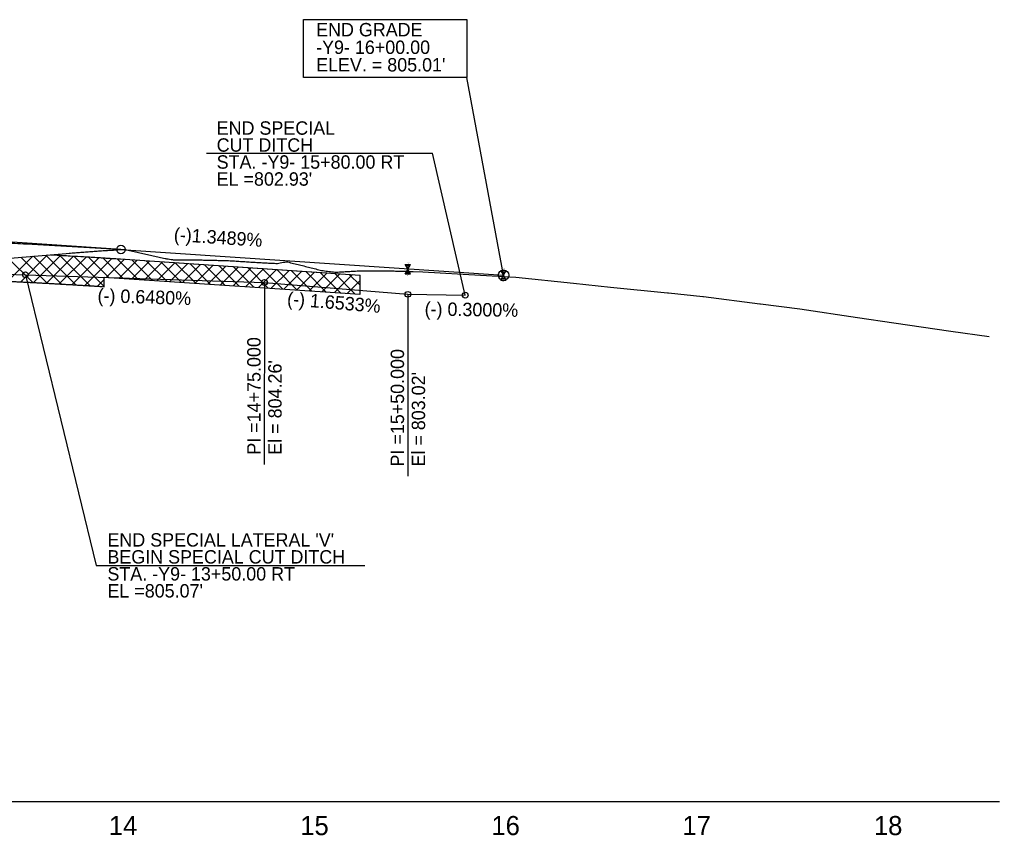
# Model space of a CAD drawing. Extents: x 579185 to 595036, y -53221 to -44640.
# Drawn here: x 591536 to 592048, y -49553 to -49126 of the extents above; entities that cross this region are included whole.
import ezdxf

# ---------------------------------------------------------------- set-up
doc = ezdxf.new("R2010")
doc.units = 0
for name, color, linetype in [('Exist Profile Cell', 7, 'Continuous'), ('Exist Vertical Profile Ground Line', 7, 'Continuous'), ('Exist Vertical Profile Horizontal Axis Label Major', 7, 'Continuous'), ('Old_Level_2', 7, 'Continuous'), ('Prop Grid Mask', 7, 'Continuous'), ('Prop Hatching', 7, 'Continuous'), ('Prop Vertical Profile Curve Label', 7, 'Continuous'), ('Prop Vertical Profile Ditch Grade Right', 7, 'Continuous'), ('Prop Vertical Profile Ditch Grade Right Label', 7, 'Continuous'), ('Prop Vertical Profile Grade', 7, 'Continuous'), ('Prop Vertical Profile Grade Label', 7, 'Continuous'), ('Prop VPI Ditch Grade Right Label', 7, 'Continuous'), ('Prop VPI Label', 7, 'Continuous')]:
    doc.layers.add(name, color=color, linetype=linetype)

msp = doc.modelspace()

# ---------------------------------------------------------------- linework, layer by layer
at = {"layer": 'Exist Profile Cell'}
msp.add_line((591188.99, -49535.12), (592048.25, -49535.12), dxfattribs=at)
at = {"layer": 'Exist Vertical Profile Ground Line'}
for points in [[(591531.14, -49251.08), (591560.27, -49248.66), (591561.87, -49248.52), (591562.64, -49248.46), (591563.41, -49248.4), (591564.18, -49248.34), (591564.96, -49248.27), (591565.73, -49248.21), (591566.5, -49248.15), (591567.27, -49248.09), (591568.05, -49248.03), (591568.82, -49247.97), (591569.59, -49247.91), (591570.36, -49247.85), (591571.13, -49247.79), (591571.91, -49247.73), (591572.78, -49247.66), (591573.45, -49247.61), (591574.22, -49247.56), (591575, -49247.51), (591575.77, -49247.46), (591576.54, -49247.41), (591577.31, -49247.35), (591578.08, -49247.3), (591578.86, -49247.25), (591579.63, -49247.2), (591580.4, -49247.15), (591581.17, -49247.1), (591581.95, -49247.05), (591582.72, -49247.01), (591583.49, -49246.96), (591584.26, -49246.91), (591585.03, -49246.86), (591585.81, -49246.82), (591586.58, -49246.77), (591587.35, -49246.72), (591588.12, -49246.68), (591588.9, -49246.63), (591589.67, -49246.59), (591590.66, -49246.53), (591591.21, -49246.65), (591591.98, -49246.83), (591592.76, -49247)], [(591592.76, -49247), (591593.53, -49247.17), (591594.3, -49247.35), (591595.07, -49247.52), (591595.84, -49247.69), (591596.62, -49247.87), (591597.39, -49248.04), (591598.16, -49248.21), (591598.93, -49248.38), (591599.71, -49248.56), (591600.48, -49248.73), (591601.25, -49248.9), (591602.02, -49249.07), (591602.79, -49249.24), (591603.57, -49249.42), (591604.34, -49249.59), (591605.11, -49249.76), (591605.88, -49249.93), (591606.66, -49250.1), (591607.43, -49250.27), (591608.2, -49250.44), (591608.97, -49250.6), (591609.74, -49250.77), (591610.52, -49250.94), (591611.29, -49251.11), (591612.06, -49251.27), (591612.46, -49251.36), (591612.83, -49251.42), (591613.61, -49251.54), (591614.38, -49251.66), (591615.15, -49251.78), (591615.92, -49251.9), (591616.3, -49251.96), (591616.69, -49251.96), (591617.47, -49251.97), (591618.24, -49251.98), (591619.01, -49251.99), (591619.78, -49252), (591620.72, -49252.01), (591621.33, -49252.01), (591622.1, -49252.02), (591622.87, -49252.02), (591623.64, -49252.02), (591624.42, -49252.03), (591625.19, -49252.03), (591625.96, -49252.04), (591626.73, -49252.04), (591627.51, -49252.05), (591628.28, -49252.05), (591629.05, -49252.06), (591629.82, -49252.07), (591630.59, -49252.07), (591631.37, -49252.08), (591632.14, -49252.09), (591632.91, -49252.1), (591633.68, -49252.11), (591634.46, -49252.13), (591635.23, -49252.15), (591636, -49252.17), (591636.77, -49252.19), (591637.54, -49252.21), (591638.32, -49252.23), (591639.09, -49252.24), (591639.86, -49252.26), (591640.63, -49252.28), (591641.41, -49252.3), (591642.18, -49252.33), (591642.95, -49252.35), (591643.72, -49252.37), (591644.49, -49252.39), (591645.27, -49252.41), (591646.04, -49252.43), (591646.81, -49252.48), (591647.58, -49252.54), (591648.35, -49252.59), (591649.13, -49252.64), (591649.9, -49252.69), (591650.67, -49252.74), (591651.44, -49252.79), (591652.22, -49252.84), (591652.99, -49252.89), (591653.76, -49252.94), (591654.53, -49252.98), (591655.3, -49253.03), (591656.08, -49253.08), (591656.85, -49253.13), (591657.62, -49253.17), (591658.39, -49253.22), (591659.17, -49253.26), (591659.94, -49253.31), (591660.71, -49253.35), (591661.48, -49253.4), (591662.25, -49253.44), (591663.03, -49253.48), (591663.8, -49253.53), (591664.57, -49253.57), (591665.34, -49253.61), (591666.12, -49253.65), (591666.89, -49253.69), (591667.66, -49253.73), (591668.43, -49253.77)], [(591668.43, -49253.77), (591669.2, -49253.81), (591669.98, -49253.85), (591670.75, -49253.88), (591671.52, -49253.73), (591672.29, -49253.58), (591673.07, -49253.44), (591673.84, -49253.29), (591674.61, -49253.14), (591675.52, -49252.96), (591676.15, -49253.12), (591676.93, -49253.3), (591677.7, -49253.49), (591678.47, -49253.68), (591679.24, -49253.87), (591680.02, -49254.06), (591680.79, -49254.25), (591681.56, -49254.44), (591682.33, -49254.63), (591683.1, -49254.83), (591683.88, -49255.02), (591684.65, -49255.21), (591685.42, -49255.41), (591686.19, -49255.6), (591686.97, -49255.8), (591687.74, -49255.99), (591688.51, -49256.19), (591689.28, -49256.38), (591690.05, -49256.58), (591690.83, -49256.78), (591691.6, -49256.98), (591692.37, -49257.17), (591693.14, -49257.37), (591693.91, -49257.49), (591694.69, -49257.61), (591695.46, -49257.73), (591696.23, -49257.84), (591697, -49257.96), (591697.78, -49258.07), (591698.16, -49258.13), (591698.55, -49258.16), (591699.32, -49258.23), (591700.09, -49258.29), (591700.86, -49258.36), (591701.71, -49258.42), (591702.41, -49258.38), (591703.18, -49258.33), (591703.95, -49258.28), (591704.73, -49258.23), (591705.5, -49258.18), (591706.27, -49258.14), (591707.04, -49258.09), (591707.81, -49258.05), (591708.59, -49258.01), (591709.36, -49257.96), (591710.13, -49257.92), (591710.9, -49257.88), (591711.68, -49257.84), (591712.45, -49257.81), (591713.22, -49257.77), (591713.63, -49257.75), (591713.99, -49257.75), (591714.76, -49257.75), (591715.54, -49257.74), (591716.31, -49257.74), (591717.08, -49257.74), (591717.85, -49257.74), (591718.63, -49257.74), (591719.4, -49257.74), (591720.17, -49257.74), (591720.94, -49257.75), (591721.71, -49257.75), (591722.49, -49257.75), (591723.26, -49257.76), (591724.03, -49257.76), (591724.8, -49257.77), (591725.58, -49257.77), (591726.35, -49257.78), (591727.12, -49257.79), (591727.89, -49257.8), (591728.66, -49257.8), (591729.1, -49257.81), (591729.44, -49257.81), (591730.21, -49257.8), (591730.98, -49257.8), (591731.75, -49257.82), (591732.53, -49257.83), (591733.3, -49257.85), (591734.07, -49257.86), (591734.84, -49257.88), (591735.61, -49257.9), (591736.39, -49257.92), (591737.16, -49257.93), (591737.93, -49257.95), (591738.7, -49257.97), (591739.48, -49257.99), (591740.25, -49258.01), (591741.02, -49258.03), (591741.79, -49258.05), (591746.89, -49258.18), (591776.93, -49259.96)], [(591776.93, -49259.96), (591795.5, -49261.06), (591825.5, -49264.18), (591844.97, -49266.21), (591874.77, -49269.23), (591875.18, -49269.27), (591893.16, -49271.1), (591893.57, -49271.15), (591923.05, -49274.95), (591923.36, -49274.99), (591943.99, -49277.65), (591974, -49282.1), (591992.99, -49284.92), (592022.91, -49289.2), (592042.92, -49292.06)]]:
    msp.add_lwpolyline(points, dxfattribs=at)
at = {"layer": 'Old_Level_2'}
for p, q in [((591738.99, -49256.88), (591737.55, -49254.38)), ((591737.55, -49254.38), (591740.43, -49254.38)), ((591738.99, -49256.88), (591740.43, -49254.38)), ((591737.55, -49259.38), (591738.99, -49256.88)), ((591737.55, -49259.38), (591740.43, -49259.38)), ((591738.03, -49255.21), (591739.95, -49255.21)), ((591738.03, -49258.55), (591739.95, -49258.55)), ((591738.51, -49256.05), (591739.47, -49256.05)), ((591738.51, -49257.72), (591739.47, -49257.72)), ((591740.43, -49259.38), (591738.99, -49256.88)), ((591788.99, -49260.04), (591787.55, -49257.54)), ((591787.55, -49257.54), (591790.43, -49257.54)), ((591788.03, -49258.37), (591789.95, -49258.37)), ((591788.51, -49259.21), (591789.47, -49259.21)), ((591788.99, -49260.04), (591790.43, -49257.54)), ((591787.55, -49262.54), (591788.99, -49260.04)), ((591787.55, -49262.54), (591790.43, -49262.54)), ((591788.03, -49261.71), (591789.95, -49261.71)), ((591788.51, -49260.88), (591789.47, -49260.88)), ((591790.43, -49262.54), (591788.99, -49260.04))]:
    msp.add_line(p, q, dxfattribs=at)
at = {"layer": 'Prop Grid Mask'}
msp.add_lwpolyline([(591684.45, -49126.46), (591769.85, -49126.46), (591769.85, -49156.65), (591684.45, -49156.65)], close=True, dxfattribs=at)
at = {"layer": 'Prop Hatching'}
for p, q in [((591529.81, -49263.19), (591542.9, -49250.1)), ((591530.07, -49251.05), (591542.86, -49263.84)), ((591536.55, -49263.52), (591550.62, -49249.46)), ((591536.71, -49250.62), (591550.33, -49264.23)), ((591543.24, -49250.07), (591557.82, -49264.65)), ((591543.29, -49263.86), (591557.53, -49249.61)), ((591549.77, -49249.53), (591565.32, -49265.09)), ((591550, -49264.22), (591564.22, -49250)), ((591556.7, -49264.59), (591570.89, -49250.4)), ((591556.88, -49249.58), (591572.85, -49265.55)), ((591563.39, -49264.97), (591577.55, -49250.81)), ((591564.39, -49250.01), (591580.24, -49265.86)), ((591570.06, -49265.37), (591584.19, -49251.24)), ((591571.91, -49250.46), (591582.61, -49261.16)), ((591579.46, -49250.94), (591590.19, -49261.67)), ((591581.42, -49261.08), (591590.81, -49251.69)), ((591587.03, -49251.43), (591597.77, -49262.18)), ((591588.05, -49261.52), (591597.44, -49252.13)), ((591588.65, -49251.54), (591698.99, -49258.98)), ((591588.65, -49251.54), (591713.99, -49259.99)), ((591594.61, -49251.94), (591605.35, -49262.69)), ((591594.67, -49261.97), (591604.06, -49252.58)), ((591601.3, -49262.42), (591610.69, -49253.03)), ((591602.19, -49252.45), (591612.94, -49263.2)), ((591607.92, -49262.86), (591617.31, -49253.47)), ((591609.77, -49252.97), (591620.52, -49263.71)), ((591614.55, -49263.31), (591623.94, -49253.92)), ((591617.35, -49253.48), (591628.1, -49264.22)), ((591621.17, -49263.76), (591630.56, -49254.37)), ((591624.94, -49253.99), (591635.68, -49264.74)), ((591632.52, -49254.5), (591643.27, -49265.25)), ((591627.8, -49264.2), (591637.18, -49254.81)), ((591634.42, -49264.65), (591643.81, -49255.26)), ((591640.1, -49255.01), (591650.85, -49265.76)), ((591641.04, -49265.1), (591650.43, -49255.71)), ((591647.67, -49265.54), (591657.06, -49256.15)), ((591647.68, -49255.52), (591658.43, -49266.27)), ((591654.29, -49265.99), (591663.68, -49256.6)), ((591655.27, -49256.03), (591666.01, -49266.78)), ((591660.92, -49266.44), (591670.31, -49257.05)), ((591662.85, -49256.55), (591673.6, -49267.29)), ((591667.54, -49266.88), (591676.93, -49257.5)), ((591670.43, -49257.06), (591681.18, -49267.8)), ((591674.17, -49267.33), (591683.55, -49257.94)), ((591678.01, -49257.57), (591688.76, -49268.32)), ((591680.79, -49267.78), (591690.18, -49258.39)), ((591685.6, -49258.08), (591696.34, -49268.83)), ((591687.41, -49268.22), (591696.8, -49258.84)), ((591693.18, -49258.59), (591703.93, -49269.34)), ((591694.04, -49268.67), (591703.43, -49259.28)), ((591700.76, -49259.1), (591711.51, -49269.85)), ((591708.34, -49259.61), (591713.99, -49265.26)), ((591576.71, -49265.79), (591580.24, -49262.26)), ((591580.24, -49266.02), (591580.24, -49261)), ((591580.24, -49261), (591713.99, -49270.02)), ((591700.66, -49269.12), (591710.05, -49259.73)), ((591707.29, -49269.57), (591713.99, -49262.86)), ((591713.99, -49270.02), (591713.99, -49259.99)), ((591713.91, -49270.01), (591713.99, -49269.93))]:
    msp.add_line(p, q, dxfattribs=at)
for points in [[(591552.28, -49249.32), (591557.31, -49249.6), (591562.35, -49249.88), (591570.3, -49250.36), (591573.22, -49250.54), (591577.5, -49250.81), (591578.87, -49250.9), (591581.26, -49251.05), (591582.28, -49251.12), (591584.34, -49251.25), (591585.36, -49251.32), (591587.15, -49251.44), (591587.9, -49251.49), (591588.66, -49251.54)], [(591363.99, -49260.24), (591365.06, -49260.23), (591366.13, -49260.21), (591367.19, -49260.2), (591369.18, -49260.18), (591371.17, -49260.17), (591373.15, -49260.15), (591375.14, -49260.13), (591377.12, -49260.12), (591379.11, -49260.11), (591381.1, -49260.09), (591383.08, -49260.08), (591385.07, -49260.08), (591387.05, -49260.07), (591389.04, -49260.06), (591391.03, -49260.06), (591393.01, -49260.06), (591395, -49260.05), (591396.98, -49260.05), (591398.97, -49260.05), (591400.96, -49260.06), (591402.94, -49260.06), (591404.93, -49260.07), (591406.91, -49260.07), (591408.9, -49260.08), (591410.89, -49260.09), (591412.87, -49260.1), (591414.86, -49260.11), (591416.84, -49260.13), (591418.83, -49260.14), (591420.82, -49260.16), (591422.8, -49260.18), (591424.79, -49260.2), (591426.77, -49260.22), (591428.76, -49260.24), (591430.75, -49260.26), (591432.73, -49260.29), (591434.72, -49260.31), (591436.71, -49260.34), (591438.69, -49260.37), (591440.68, -49260.4), (591442.66, -49260.43), (591444.65, -49260.47), (591446.64, -49260.5), (591448.62, -49260.54), (591450.61, -49260.57), (591452.59, -49260.61), (591454.58, -49260.65), (591456.57, -49260.69), (591458.55, -49260.74), (591460.54, -49260.78), (591462.52, -49260.83), (591464.51, -49260.87), (591466.5, -49260.92), (591468.48, -49260.97), (591470.47, -49261.02), (591472.45, -49261.08), (591474.44, -49261.13), (591476.43, -49261.18), (591478.41, -49261.24), (591480.4, -49261.3), (591482.38, -49261.36), (591484.37, -49261.42), (591486.36, -49261.48), (591488.34, -49261.55), (591490.33, -49261.61), (591492.31, -49261.68), (591494.3, -49261.75), (591496.29, -49261.81), (591498.27, -49261.89), (591500.26, -49261.96), (591502.24, -49262.03), (591504.23, -49262.11), (591506.22, -49262.18), (591508.2, -49262.26), (591510.19, -49262.34), (591512.17, -49262.42), (591514.16, -49262.5), (591516.15, -49262.58), (591518.13, -49262.67), (591520.12, -49262.75), (591522.1, -49262.84), (591524.09, -49262.93), (591526.08, -49263.02), (591528.06, -49263.11), (591530.05, -49263.21), (591532.03, -49263.3), (591534.02, -49263.4), (591536.01, -49263.49), (591537.99, -49263.59), (591539.98, -49263.69), (591541.96, -49263.79), (591543.95, -49263.89), (591545.94, -49264), (591547.92, -49264.1), (591549.91, -49264.21), (591551.89, -49264.32), (591553.88, -49264.43), (591555.87, -49264.54), (591557.85, -49264.65), (591559.84, -49264.77), (591561.83, -49264.88), (591563.81, -49265), (591565.8, -49265.12), (591567.78, -49265.24), (591569.77, -49265.36), (591571.76, -49265.48), (591573.74, -49265.6), (591575.73, -49265.73), (591577.23, -49265.82), (591578.74, -49265.92), (591580.24, -49266.02)]]:
    msp.add_open_spline(points, degree=3, dxfattribs=at)
at = {"layer": 'Prop Vertical Profile Curve Label'}
msp.add_line((591788.99, -49260.04), (591769.85, -49156.65), dxfattribs=at)
msp.add_circle((591588.99, -49246.55), 2.25, dxfattribs=at)
at = {"layer": 'Prop Vertical Profile Ditch Grade Right'}
for points in [[(591413.99, -49255.27), (591513.99, -49258.97), (591538.99, -49259.77)], [(591538.99, -49259.77), (591663.99, -49263.82), (591738.99, -49270.02), (591768.99, -49270.47)]]:
    msp.add_lwpolyline(points, dxfattribs=at)
at = {"layer": 'Prop Vertical Profile Ditch Grade Right Label'}
for p, q in [((591633.72, -49196.33), (591751.82, -49196.33)), ((591768.99, -49270.47), (591751.82, -49196.33)), ((591538.99, -49259.77), (591575.96, -49411.68)), ((591663.99, -49263.82), (591663.9, -49358.89)), ((591738.99, -49270.02), (591738.9, -49365.09)), ((591575.96, -49411.68), (591716.52, -49411.68))]:
    msp.add_line(p, q, dxfattribs=at)
at = {"layer": 'Prop Vertical Profile Grade'}
msp.add_line((591588.99, -49246.55), (591788.99, -49260.04), dxfattribs=at)
msp.add_spline([(591288.99, -49242.07), (591294.99, -49241.85), (591300.99, -49241.65), (591306.99, -49241.45), (591312.99, -49241.27), (591318.99, -49241.1), (591324.99, -49240.95), (591330.99, -49240.8), (591336.99, -49240.67), (591342.99, -49240.55), (591348.99, -49240.45), (591354.99, -49240.35), (591360.99, -49240.27), (591366.99, -49240.21), (591372.99, -49240.15), (591378.99, -49240.11), (591384.99, -49240.08), (591390.99, -49240.06), (591396.99, -49240.06), (591402.99, -49240.06), (591408.99, -49240.08), (591414.99, -49240.12), (591420.99, -49240.16), (591426.99, -49240.22), (591432.99, -49240.29), (591438.99, -49240.37), (591444.99, -49240.47), (591450.99, -49240.58), (591456.99, -49240.7), (591462.99, -49240.83), (591468.99, -49240.98), (591474.99, -49241.14), (591480.99, -49241.31), (591486.99, -49241.49), (591492.99, -49241.69), (591498.99, -49241.9), (591504.99, -49242.12), (591510.99, -49242.36), (591516.99, -49242.6), (591522.99, -49242.86), (591528.99, -49243.14), (591534.99, -49243.42), (591540.99, -49243.72), (591546.99, -49244.03), (591552.99, -49244.35), (591558.99, -49244.69), (591564.99, -49245.03), (591570.99, -49245.4), (591576.99, -49245.77), (591582.99, -49246.15), (591588.99, -49246.55)], degree=3, dxfattribs=at)
at = {"layer": 'Prop VPI Ditch Grade Right Label'}
for centre in [(591538.99, -49259.77), (591663.99, -49263.82), (591738.99, -49270.02), (591768.99, -49270.47)]:
    msp.add_circle(centre, 1.5, dxfattribs=at)
at = {"layer": 'Prop VPI Label'}
msp.add_line((591588.99, -49246.55), (591441.73, -49236.62), dxfattribs=at)
msp.add_circle((591788.99, -49260.04), 2.75, dxfattribs=at)

# ---------------------------------------------------------------- texts
at = {"layer": 'Exist Vertical Profile Horizontal Axis Label Major'}
for s, p in [('14', (591582.64, -49552.62)), ('15', (591682.73, -49552.62)), ('16', (591782.67, -49552.62)), ('17', (591882.53, -49552.62)), ('18', (591982.65, -49552.62))]:
    msp.add_text(s, height=10, dxfattribs=at).set_placement(p)
at = {"layer": 'Old_Level_2'}
for p in [(591738.76, -49254.22), (591738.56, -49260.39), (591788.76, -49257.38), (591788.56, -49263.55)]:
    msp.add_text('6"', height=0.8, dxfattribs=at).set_placement(p)
at = {"layer": 'Prop Vertical Profile Ditch Grade Right'}
for s, p in [('END SPECIAL ', (591639.02, -49186.62)), ('CUT DITCH', (591639.02, -49195.5)), ('STA. -Y9- 15+80.00 RT ', (591639.02, -49204.37)), ("EL =802.93'", (591639.02, -49213.25)), ("END SPECIAL LATERAL 'V'", (591581.9, -49401.84)), ('BEGIN SPECIAL CUT DITCH', (591581.9, -49410.71)), ('STA. -Y9- 13+50.00 RT ', (591581.9, -49419.58)), ("EL =805.07'", (591581.9, -49428.46))]:
    msp.add_text(s, height=7, dxfattribs=at).set_placement(p)
at = {"layer": 'Prop Vertical Profile Ditch Grade Right Label'}
for s, rotation, p in [('(-) 0.6480%', 358.1443, (591576.65, -49274.05)), ('(-) 1.6533%', 355.2743, (591675.65, -49275.7)), ('(-) 0.3000%', 359.1406, (591747.71, -49281.09))]:
    msp.add_text(s, height=7, rotation=rotation, dxfattribs=at).set_placement(p)
at = {"layer": 'Prop Vertical Profile Grade Label'}
msp.add_text('(-)1.3489%', height=7, rotation=356.1417, dxfattribs=at).set_placement((591616.47, -49242.13))
at = {"layer": 'Prop VPI Ditch Grade Right Label'}
for s, p in [('PI =14+75.000', (591661.99, -49353.82)), ('PI =15+50.000', (591736.99, -49360.02)), ("El = 804.26'", (591672.99, -49353.82)), ("El = 803.02'", (591747.99, -49360.02))]:
    msp.add_text(s, height=7, rotation=90, dxfattribs=at).set_placement(p)
at = {"layer": 'Prop VPI Label'}
for s, p in [('END GRADE', (591691.01, -49135.22)), ('-Y9- 16+00.00', (591691.01, -49144.4)), ("ELEV. = 805.01'", (591691.01, -49153.57))]:
    msp.add_text(s, height=7, dxfattribs=at).set_placement(p)

doc.saveas('drawing.dxf')
